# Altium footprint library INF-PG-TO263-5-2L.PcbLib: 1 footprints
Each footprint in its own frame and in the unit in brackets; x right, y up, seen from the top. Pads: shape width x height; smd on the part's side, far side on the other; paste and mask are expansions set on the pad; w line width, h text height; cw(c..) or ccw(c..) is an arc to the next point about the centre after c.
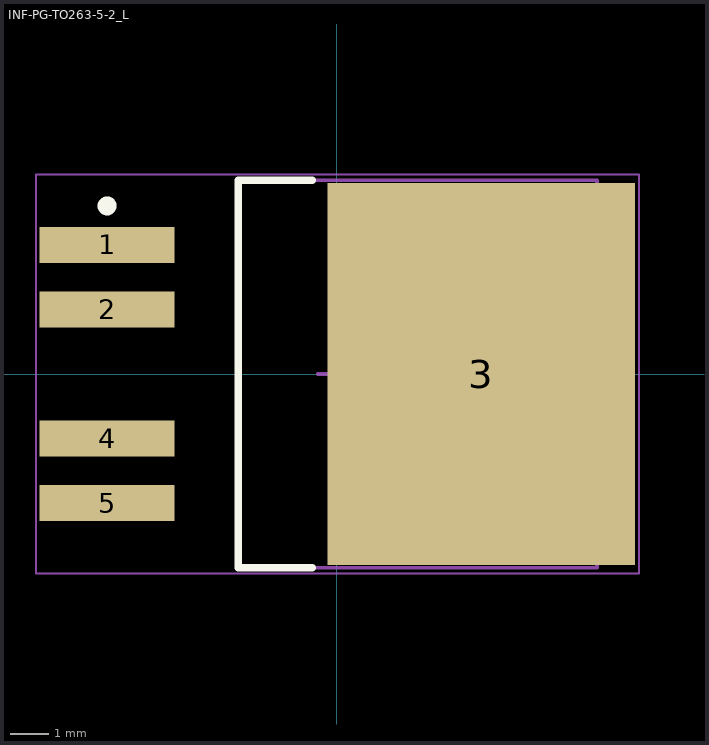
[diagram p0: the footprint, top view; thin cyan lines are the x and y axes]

## INF-PG-TO263-5-2_L [mm] "DPAK, 5-Leads, Body 10x9.25mm, Pitch 1.7mm, IPC High Density"
height 4.4
pads (5):
  rect 3.55x0.95 smd: 1(-6.05,3.4) 2(-6.05,1.7) 4(-6.05,-1.7) 5(-6.05,-3.4)
  rect 8.1x10.05 smd: 3(3.8,0)
Top Overlay:
  circle w0.25: c-6.05,4.425 r0.125
  lines w0.2: -0.65,-5.1 -2.6,-5.1 -2.6,5.1 -0.65,5.1
Mechanical 13:
  lines w0.1: -2.6,-5.1 -2.6,5.1 6.85,5.1 6.85,-5.1 -2.6,-5.1
Mechanical 15:
  lines w0.05: -7.925,-5.25 -7.925,5.25 7.95,5.25 7.95,-5.25 -7.925,-5.25
  lines w0.1: -0.5,0 0.5,0 ; 0,-0.5 0,0.5
3D body: height 4.4, standoff 0.1, extent -2.6,-5.1 6.85,5.1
